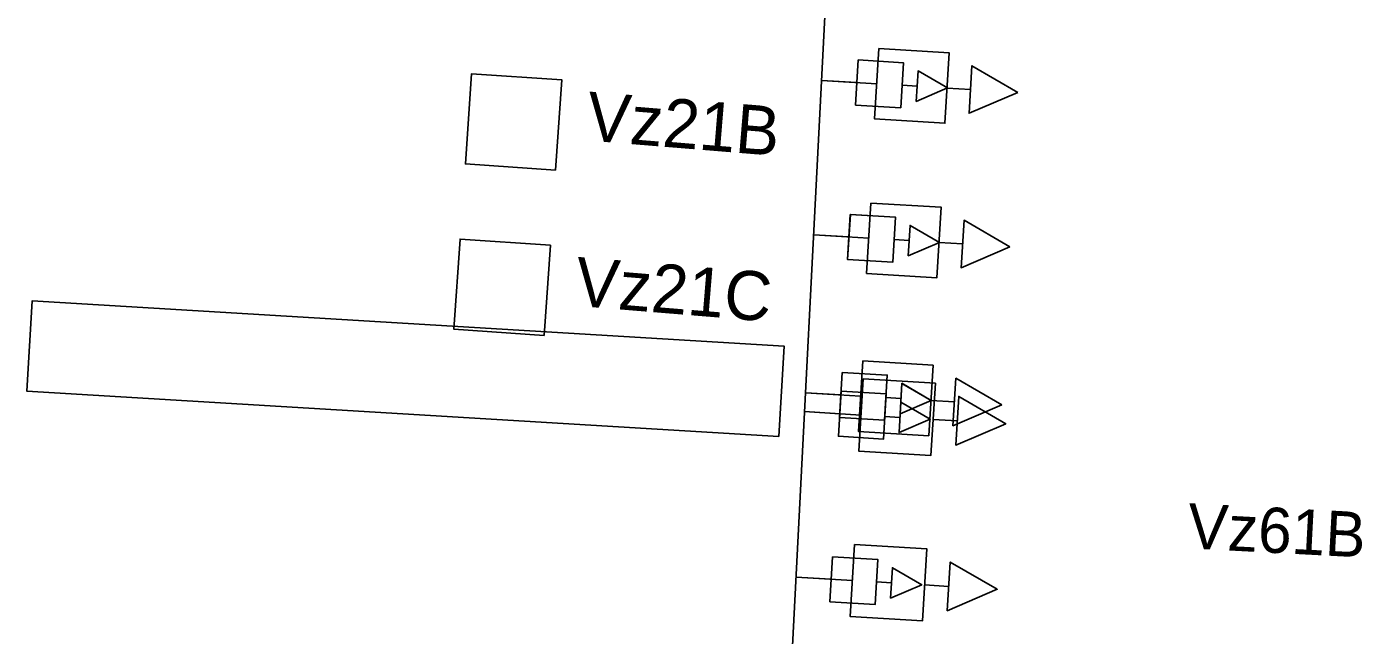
# Model space of a CAD drawing. Extents: x 647787 to 668496, y 640478 to 654412.
# Drawn here: x 661415.4 to 661504.1, y 647337 to 647377.4 of the extents above; entities that cross this region are included whole.
import ezdxf

# ---------------------------------------------------------------- set-up
doc = ezdxf.new("R2010")
doc.units = 0
for name, color, linetype in [('TEMP_DETECTION ZONE', 7, 'Continuous'), ('TEMP_DETECTION ZONE_Stage 2', 7, 'Continuous'), ('TEMP_SIGNAL_HEAD_PED STAGES 1C', 7, 'Continuous'), ('TEMP_SIGNAL_HEAD_STAGE 2', 7, 'Continuous'), ('TEMP_SIGNAL_HEAD_STAGE 2 SHILO', 7, 'Continuous'), ('TEMP_SIGNAL_HEAD_STAGE 3 SHILO', 7, 'Continuous'), ('TEMP_SIGNAL_HEAD_STAGE 4 SHILO', 7, 'Continuous'), ('TEMP_SIGNAL_POLE_STAGE 2-3', 7, 'Continuous'), ('TEMP_SIGNAL_POLES_STAGE 1B', 7, 'Continuous')]:
    doc.layers.add(name, color=color, linetype=linetype)

msp = doc.modelspace()

# ---------------------------------------------------------------- linework, layer by layer
at = {"layer": 'TEMP_DETECTION ZONE'}
msp.add_lwpolyline([(661465.346, 647350.185), (661465.707, 647356.174), (661415.798, 647359.187), (661415.436, 647353.198)], close=True, dxfattribs=at)
msp.add_lwpolyline([(661465.346, 647350.185), (661465.707, 647356.174), (661415.798, 647359.187), (661415.436, 647353.198)], close=True, dxfattribs=at)
at = {"layer": 'TEMP_SIGNAL_HEAD_PED STAGES 1C'}
for points in [[(661469.482, 647353.191), (661469.301, 647350.196), (661472.296, 647350.016), (661472.476, 647353.01)], [(661469.482, 647353.191), (661469.301, 647350.196), (661472.296, 647350.016), (661472.476, 647353.01)], [(661475.396, 647351.331), (661473.445, 647352.462), (661473.323, 647350.443)], [(661475.396, 647351.331), (661473.445, 647352.462), (661473.323, 647350.443)], [(661468.915, 647342.205), (661468.734, 647339.211), (661471.728, 647339.03), (661471.909, 647342.024)], [(661468.915, 647342.205), (661468.734, 647339.211), (661471.728, 647339.03), (661471.909, 647342.024)], [(661474.829, 647340.345), (661472.878, 647341.477), (661472.756, 647339.457)], [(661474.829, 647340.345), (661472.878, 647341.477), (661472.756, 647339.457)]]:
    msp.add_lwpolyline(points, close=True, dxfattribs=at)
for points in [[(661467.051, 647351.835), (661469.391, 647351.694)], [(661467.051, 647351.835), (661469.391, 647351.694)], [(661473.323, 647350.443), (661473.445, 647352.462), (661475.396, 647351.331), (661473.323, 647350.443)], [(661473.323, 647350.443), (661473.445, 647352.462), (661475.396, 647351.331), (661473.323, 647350.443)], [(661472.386, 647351.513), (661473.384, 647351.453)], [(661472.386, 647351.513), (661473.384, 647351.453)], [(661472.756, 647339.457), (661472.878, 647341.477), (661474.829, 647340.345), (661472.756, 647339.457)], [(661472.756, 647339.457), (661472.878, 647341.477), (661474.829, 647340.345), (661472.756, 647339.457)], [(661466.484, 647340.849), (661468.824, 647340.708)], [(661466.484, 647340.849), (661468.824, 647340.708)], [(661471.819, 647340.527), (661472.817, 647340.467)], [(661471.819, 647340.527), (661472.817, 647340.467)]]:
    msp.add_lwpolyline(points, dxfattribs=at)
at = {"layer": 'TEMP_SIGNAL_HEAD_STAGE 2'}
for points in [[(661470.617, 647375.175), (661470.436, 647372.181), (661473.431, 647372), (661473.611, 647374.994)], [(661470.617, 647375.175), (661470.436, 647372.181), (661473.431, 647372), (661473.611, 647374.994)], [(661470.617, 647375.175), (661470.436, 647372.181), (661473.431, 647372), (661473.611, 647374.994)], [(661470.619, 647375.177), (661470.438, 647372.183), (661473.433, 647372.002), (661473.614, 647374.996)], [(661476.531, 647373.315), (661474.58, 647374.447), (661474.458, 647372.427)], [(661476.531, 647373.315), (661474.58, 647374.447), (661474.458, 647372.427)], [(661476.531, 647373.315), (661474.58, 647374.447), (661474.458, 647372.427)], [(661476.534, 647373.317), (661474.582, 647374.449), (661474.46, 647372.429)], [(661470.088, 647364.926), (661469.907, 647361.931), (661472.901, 647361.75), (661473.082, 647364.745)], [(661470.088, 647364.926), (661469.907, 647361.931), (661472.901, 647361.75), (661473.082, 647364.745)], [(661470.088, 647364.926), (661469.907, 647361.931), (661472.901, 647361.75), (661473.082, 647364.745)], [(661470.09, 647364.928), (661469.909, 647361.933), (661472.904, 647361.752), (661473.085, 647364.747)], [(661476.002, 647363.066), (661474.051, 647364.197), (661473.929, 647362.178)], [(661476.002, 647363.066), (661474.051, 647364.197), (661473.929, 647362.178)], [(661476.002, 647363.066), (661474.051, 647364.197), (661473.929, 647362.178)], [(661476.005, 647363.068), (661474.053, 647364.199), (661473.931, 647362.179)], [(661469.546, 647354.439), (661469.365, 647351.445), (661472.36, 647351.264), (661472.541, 647354.259)], [(661469.546, 647354.439), (661469.365, 647351.445), (661472.36, 647351.264), (661472.541, 647354.259)], [(661469.546, 647354.439), (661469.365, 647351.445), (661472.36, 647351.264), (661472.541, 647354.259)], [(661469.549, 647354.441), (661469.368, 647351.447), (661472.362, 647351.266), (661472.543, 647354.26)], [(661475.461, 647352.58), (661473.51, 647353.711), (661473.388, 647351.691)], [(661475.461, 647352.58), (661473.51, 647353.711), (661473.388, 647351.691)], [(661475.461, 647352.58), (661473.51, 647353.711), (661473.388, 647351.691)], [(661475.463, 647352.581), (661473.512, 647353.713), (661473.39, 647351.693)]]:
    msp.add_lwpolyline(points, close=True, dxfattribs=at)
for points in [[(661474.458, 647372.427), (661474.58, 647374.447), (661476.531, 647373.315), (661474.458, 647372.427)], [(661474.458, 647372.427), (661474.58, 647374.447), (661476.531, 647373.315), (661474.458, 647372.427)], [(661474.458, 647372.427), (661474.58, 647374.447), (661476.531, 647373.315), (661474.458, 647372.427)], [(661474.46, 647372.429), (661474.582, 647374.449), (661476.534, 647373.317), (661474.46, 647372.429)], [(661468.186, 647373.819), (661470.526, 647373.678)], [(661468.186, 647373.819), (661470.526, 647373.678)], [(661468.186, 647373.819), (661470.526, 647373.678)], [(661468.189, 647373.821), (661470.529, 647373.68)], [(661473.521, 647373.497), (661474.519, 647373.437)], [(661473.521, 647373.497), (661474.519, 647373.437)], [(661473.521, 647373.497), (661474.519, 647373.437)], [(661473.523, 647373.499), (661474.521, 647373.439)], [(661467.657, 647363.57), (661469.997, 647363.429)], [(661467.657, 647363.57), (661469.997, 647363.429)], [(661467.657, 647363.57), (661469.997, 647363.429)], [(661467.66, 647363.572), (661470, 647363.43)], [(661473.929, 647362.178), (661474.051, 647364.197), (661476.002, 647363.066), (661473.929, 647362.178)], [(661473.929, 647362.178), (661474.051, 647364.197), (661476.002, 647363.066), (661473.929, 647362.178)], [(661473.929, 647362.178), (661474.051, 647364.197), (661476.002, 647363.066), (661473.929, 647362.178)], [(661473.931, 647362.179), (661474.053, 647364.199), (661476.005, 647363.068), (661473.931, 647362.179)], [(661472.992, 647363.248), (661473.99, 647363.187)], [(661472.992, 647363.248), (661473.99, 647363.187)], [(661472.992, 647363.248), (661473.99, 647363.187)], [(661472.994, 647363.25), (661473.992, 647363.189)], [(661473.388, 647351.691), (661473.51, 647353.711), (661475.461, 647352.58), (661473.388, 647351.691)], [(661473.388, 647351.691), (661473.51, 647353.711), (661475.461, 647352.58), (661473.388, 647351.691)], [(661473.388, 647351.691), (661473.51, 647353.711), (661475.461, 647352.58), (661473.388, 647351.691)], [(661473.39, 647351.693), (661473.512, 647353.713), (661475.463, 647352.581), (661473.39, 647351.693)], [(661467.116, 647353.083), (661469.456, 647352.942)], [(661467.116, 647353.083), (661469.456, 647352.942)], [(661467.116, 647353.083), (661469.456, 647352.942)], [(661467.118, 647353.085), (661469.458, 647352.944)], [(661472.45, 647352.761), (661473.449, 647352.701)], [(661472.45, 647352.761), (661473.449, 647352.701)], [(661472.45, 647352.761), (661473.449, 647352.701)], [(661472.453, 647352.763), (661473.451, 647352.703)]]:
    msp.add_lwpolyline(points, dxfattribs=at)
at = {"layer": 'TEMP_SIGNAL_HEAD_STAGE 2 SHILO'}
for points in [[(661471.98, 647375.931), (661471.693, 647371.259), (661476.364, 647370.972), (661476.651, 647375.643)], [(661471.98, 647375.931), (661471.693, 647371.259), (661476.364, 647370.972), (661476.651, 647375.643)], [(661481.204, 647373.019), (661478.162, 647374.787), (661477.968, 647371.637)], [(661481.204, 647373.019), (661478.162, 647374.787), (661477.968, 647371.637)], [(661471.451, 647365.681), (661471.164, 647361.01), (661475.835, 647360.723), (661476.122, 647365.394)], [(661471.451, 647365.681), (661471.164, 647361.01), (661475.835, 647360.723), (661476.122, 647365.394)], [(661480.675, 647362.77), (661477.632, 647364.538), (661477.439, 647361.387)], [(661480.675, 647362.77), (661477.632, 647364.538), (661477.439, 647361.387)], [(661470.91, 647355.195), (661470.623, 647350.523), (661475.294, 647350.236), (661475.581, 647354.908)], [(661470.91, 647355.195), (661470.623, 647350.523), (661475.294, 647350.236), (661475.581, 647354.908)], [(661480.133, 647352.283), (661477.091, 647354.052), (661476.897, 647350.901)], [(661480.133, 647352.283), (661477.091, 647354.052), (661476.897, 647350.901)]]:
    msp.add_lwpolyline(points, close=True, dxfattribs=at)
for points in [[(661468.186, 647373.819), (661471.837, 647373.595)], [(661468.186, 647373.819), (661471.837, 647373.595)], [(661476.508, 647373.308), (661478.065, 647373.212)], [(661476.508, 647373.308), (661478.065, 647373.212)], [(661467.657, 647363.57), (661471.307, 647363.345)], [(661467.657, 647363.57), (661471.307, 647363.345)], [(661475.979, 647363.058), (661477.536, 647362.963)], [(661475.979, 647363.058), (661477.536, 647362.963)], [(661467.116, 647353.083), (661470.766, 647352.859)], [(661467.116, 647353.083), (661470.766, 647352.859)], [(661475.437, 647352.572), (661476.994, 647352.476)], [(661475.437, 647352.572), (661476.994, 647352.476)]]:
    msp.add_lwpolyline(points, dxfattribs=at)
at = {"layer": 'TEMP_SIGNAL_HEAD_STAGE 3 SHILO'}
for points in [[(661470.94, 647354.005), (661470.651, 647349.213), (661475.442, 647348.924), (661475.731, 647353.715)], [(661470.94, 647354.005), (661470.651, 647349.213), (661475.442, 647348.924), (661475.731, 647353.715)], [(661480.403, 647351.029), (661477.281, 647352.839), (661477.086, 647349.608)], [(661480.403, 647351.029), (661477.281, 647352.839), (661477.086, 647349.608)], [(661470.373, 647343.019), (661470.084, 647338.228), (661474.875, 647337.938), (661475.164, 647342.73)], [(661470.373, 647343.019), (661470.084, 647338.228), (661474.875, 647337.938), (661475.164, 647342.73)], [(661479.836, 647340.043), (661476.714, 647341.853), (661476.519, 647338.622)], [(661479.836, 647340.043), (661476.714, 647341.853), (661476.519, 647338.622)]]:
    msp.add_lwpolyline(points, close=True, dxfattribs=at)
for points in [[(661477.086, 647349.608), (661477.281, 647352.839), (661480.403, 647351.029), (661477.086, 647349.608)], [(661477.086, 647349.608), (661477.281, 647352.839), (661480.403, 647351.029), (661477.086, 647349.608)], [(661467.051, 647351.835), (661470.795, 647351.609)], [(661467.051, 647351.835), (661470.795, 647351.609)], [(661475.587, 647351.32), (661477.184, 647351.223)], [(661475.587, 647351.32), (661477.184, 647351.223)], [(661476.519, 647338.622), (661476.714, 647341.853), (661479.836, 647340.043), (661476.519, 647338.622)], [(661476.519, 647338.622), (661476.714, 647341.853), (661479.836, 647340.043), (661476.519, 647338.622)], [(661466.484, 647340.849), (661470.228, 647340.623)], [(661466.484, 647340.849), (661470.228, 647340.623)], [(661475.02, 647340.334), (661476.617, 647340.237)], [(661475.02, 647340.334), (661476.617, 647340.237)]]:
    msp.add_lwpolyline(points, dxfattribs=at)
at = {"layer": 'TEMP_SIGNAL_HEAD_STAGE 4 SHILO'}
for points in [[(661470.94, 647354.005), (661470.651, 647349.213), (661475.442, 647348.924), (661475.731, 647353.715)], [(661470.94, 647354.005), (661470.651, 647349.213), (661475.442, 647348.924), (661475.731, 647353.715)], [(661480.403, 647351.029), (661477.281, 647352.839), (661477.086, 647349.608)], [(661480.403, 647351.029), (661477.281, 647352.839), (661477.086, 647349.608)], [(661470.373, 647343.019), (661470.084, 647338.228), (661474.875, 647337.938), (661475.164, 647342.73)], [(661470.373, 647343.019), (661470.084, 647338.228), (661474.875, 647337.938), (661475.164, 647342.73)], [(661479.836, 647340.043), (661476.714, 647341.853), (661476.519, 647338.622)], [(661479.836, 647340.043), (661476.714, 647341.853), (661476.519, 647338.622)]]:
    msp.add_lwpolyline(points, close=True, dxfattribs=at)
for points in [[(661477.086, 647349.608), (661477.281, 647352.839), (661480.403, 647351.029), (661477.086, 647349.608)], [(661477.086, 647349.608), (661477.281, 647352.839), (661480.403, 647351.029), (661477.086, 647349.608)], [(661467.051, 647351.835), (661470.795, 647351.609)], [(661467.051, 647351.835), (661470.795, 647351.609)], [(661475.587, 647351.32), (661477.184, 647351.223)], [(661475.587, 647351.32), (661477.184, 647351.223)], [(661476.519, 647338.622), (661476.714, 647341.853), (661479.836, 647340.043), (661476.519, 647338.622)], [(661476.519, 647338.622), (661476.714, 647341.853), (661479.836, 647340.043), (661476.519, 647338.622)], [(661466.484, 647340.849), (661470.228, 647340.623)], [(661466.484, 647340.849), (661470.228, 647340.623)], [(661475.02, 647340.334), (661476.617, 647340.237)], [(661475.02, 647340.334), (661476.617, 647340.237)]]:
    msp.add_lwpolyline(points, dxfattribs=at)
at = {"layer": 'TEMP_SIGNAL_POLE_STAGE 2-3'}
msp.add_line((661469.389, 647397.115), (661463.219, 647277.596), dxfattribs=at)
msp.add_line((661469.389, 647397.115), (661463.219, 647277.596), dxfattribs=at)
at = {"layer": 'TEMP_SIGNAL_POLES_STAGE 1B'}
for points in [[(661450.532, 647367.862), (661444.546, 647368.278), (661444.962, 647374.263), (661450.948, 647373.847)], [(661449.769, 647356.888), (661443.783, 647357.304), (661444.199, 647363.289), (661450.185, 647362.873)]]:
    msp.add_lwpolyline(points, close=True, dxfattribs=at)

# ---------------------------------------------------------------- texts
at = {"layer": 'TEMP_DETECTION ZONE_Stage 2'}
msp.add_text('Vz61B', height=3, rotation=357.00619, dxfattribs=at).set_placement((661492.409, 647342.763))
at = {"layer": 'TEMP_SIGNAL_POLES_STAGE 1B'}
for s, p in [('Vz21B', (661452.501, 647369.84)), ('Vz21C', (661451.738, 647358.866))]:
    msp.add_text(s, height=3.25, rotation=355.32723, dxfattribs=at).set_placement(p)

doc.saveas('drawing.dxf')
